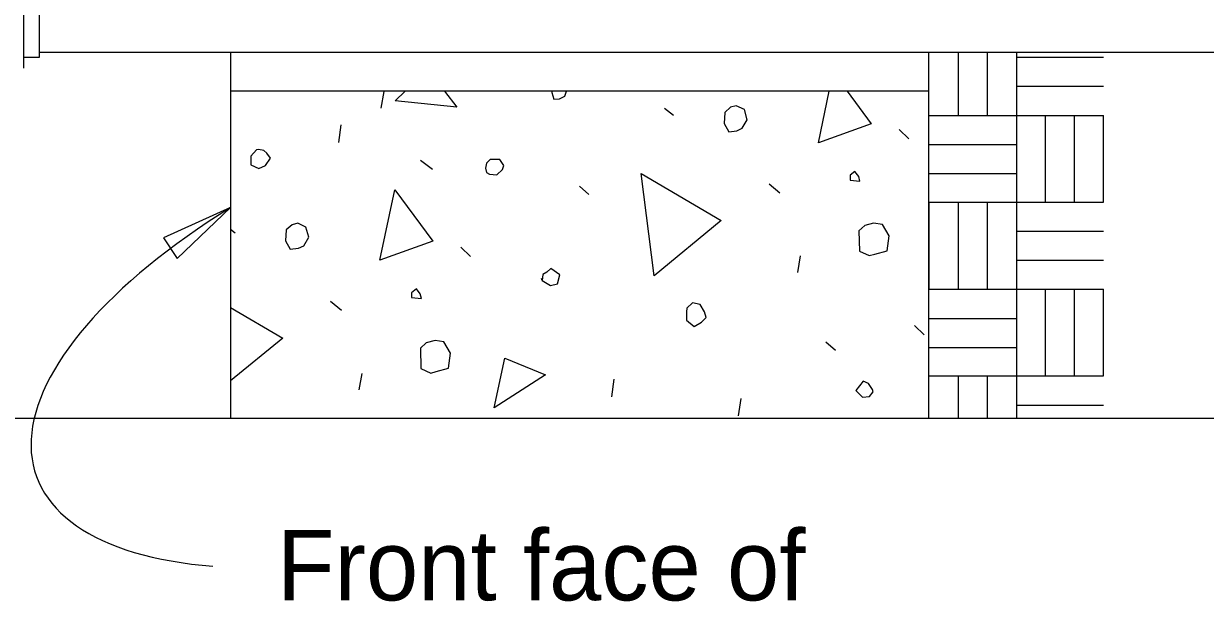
# Model space of a CAD drawing. Extents: x 112544 to 112597.1, y 111084 to 111107.1.
# Drawn here: x 112569.508 to 112572.046, y 111097.897 to 111099.138 of the extents above; entities that cross this region are included whole.
import ezdxf

# ---------------------------------------------------------------- set-up
doc = ezdxf.new("R2010")
doc.units = 0
for name, color, linetype in [('Dimension', 7, 'Continuous'), ('Lighting', 7, 'Continuous'), ('Miscellaneous', 7, 'Continuous'), ('SupstrConc', 7, 'Continuous')]:
    doc.layers.add(name, color=color, linetype=linetype)

msp = doc.modelspace()

# ---------------------------------------------------------------- linework, layer by layer
at = {"layer": 'Dimension'}
msp.add_lwpolyline([(112569.9525, 111098.7429), (112569.8082, 111098.6775), (112569.8378, 111098.6336)], close=True, dxfattribs=at)
msp.add_lwpolyline([(112572.7335, 111098.2898), (112569.4119, 111098.2898), (112569.4119, 111098.3673), (112569.3781, 111098.2898), (112569.3444, 111098.2123), (112569.3444, 111098.2898), (112564.9314, 111098.2898)], dxfattribs=at)
msp.add_ellipse((112570.5602, 111098.5306), major_axis=(1.0252, 0.3641), ratio=0.417881, start_param=2.049946, end_param=3.892568, dxfattribs=at)
at = {"layer": 'Lighting'}
for p, q in [((112569.5079, 111099.1926), (112569.5079, 111099.0427)), ((112569.5413, 111099.1697), (112569.5413, 111099.0655)), ((112569.5413, 111099.0655), (112569.5079, 111099.0655)), ((112572.656, 111099.076), (112569.5413, 111099.076))]:
    msp.add_line(p, q, dxfattribs=at)
at = {"layer": 'Miscellaneous'}
for p, q in [((112571.515, 111099.076), (112571.515, 111098.9411)), ((112571.5775, 111099.076), (112571.5775, 111098.9411)), ((112571.6413, 111098.9411), (112571.6413, 111099.076)), ((112571.6413, 111099.066), (112571.8275, 111099.066)), ((112571.4525, 111098.9927), (112569.9525, 111098.9927)), ((112570.2762, 111098.9566), (112570.2823, 111098.9919)), ((112571.6413, 111099.0035), (112571.8275, 111099.0035)), ((112570.8844, 111098.9566), (112570.9041, 111098.9411)), ((112571.4525, 111098.941), (112571.6413, 111098.941)), ((112571.6413, 111098.5673), (112571.6413, 111098.941)), ((112571.6413, 111098.941), (112571.8275, 111098.941)), ((112571.7025, 111098.7548), (112571.7025, 111098.941)), ((112571.765, 111098.7548), (112571.765, 111098.941)), ((112571.8275, 111098.7548), (112571.8275, 111098.941)), ((112570.1846, 111098.8829), (112570.1901, 111098.9206)), ((112571.3885, 111098.9105), (112571.4095, 111098.8902)), ((112571.4525, 111098.8785), (112571.6413, 111098.8785)), ((112570.3605, 111098.8447), (112570.3863, 111098.8257)), ((112571.4525, 111098.816), (112571.6413, 111098.816)), ((112570.7017, 111098.7886), (112570.722, 111098.7707)), ((112571.1091, 111098.7942), (112571.1325, 111098.7746)), ((112571.4525, 111098.7548), (112571.8275, 111098.7548)), ((112571.4525, 111098.7548), (112571.4525, 111098.5673)), ((112571.515, 111098.7548), (112571.515, 111098.5673)), ((112571.5775, 111098.7548), (112571.5775, 111098.5673)), ((112569.9525, 111098.6965), (112569.9623, 111098.6888)), ((112571.6413, 111098.6923), (112571.8275, 111098.6923)), ((112570.4468, 111098.6581), (112570.4677, 111098.6379)), ((112571.1705, 111098.6036), (112571.1766, 111098.6389)), ((112571.6413, 111098.6298), (112571.8275, 111098.6298)), ((112571.4525, 111098.5673), (112571.6413, 111098.5673)), ((112571.6413, 111098.5673), (112571.8275, 111098.5673)), ((112571.6413, 111098.2898), (112571.6413, 111098.5673)), ((112571.7025, 111098.381), (112571.7025, 111098.5673)), ((112571.765, 111098.381), (112571.765, 111098.5673)), ((112571.8275, 111098.381), (112571.8275, 111098.5673)), ((112570.1673, 111098.5418), (112570.1907, 111098.5222)), ((112571.4525, 111098.5048), (112571.6413, 111098.5048)), ((112571.4211, 111098.4896), (112571.4421, 111098.4693)), ((112571.2313, 111098.4542), (112571.2516, 111098.4364)), ((112571.4525, 111098.4423), (112571.6413, 111098.4423)), ((112570.2288, 111098.3512), (112570.2348, 111098.3865)), ((112570.7712, 111098.3361), (112570.7766, 111098.3738)), ((112571.4525, 111098.381), (112571.8275, 111098.381)), ((112571.515, 111098.3811), (112571.515, 111098.2898)), ((112571.5775, 111098.3811), (112571.5775, 111098.2898)), ((112571.0435, 111098.2952), (112571.049, 111098.3329)), ((112571.6413, 111098.3185), (112571.8275, 111098.3185))]:
    msp.add_line(p, q, dxfattribs=at)
for points in [[(112570.3056, 111098.9723), (112570.3276, 111098.9927)], [(112570.4118, 111098.9927), (112570.4387, 111098.9588), (112570.3056, 111098.9723)], [(112570.6425, 111098.9901), (112570.6464, 111098.9756), (112570.6591, 111098.9764), (112570.6705, 111098.9821), (112570.6741, 111098.9927)], [(112570.6427, 111098.9927), (112570.6425, 111098.9901)], [(112571.215, 111098.8821), (112571.2384, 111098.9927)], [(112571.2768, 111098.9927), (112571.3283, 111098.9228), (112571.215, 111098.8821)], [(112571.0138, 111098.9472), (112571.0123, 111098.9236), (112571.0223, 111098.9055), (112571.0399, 111098.9076), (112571.0513, 111098.9133), (112571.0619, 111098.9317), (112571.0561, 111098.9534), (112571.0384, 111098.9616), (112571.0263, 111098.9584), (112571.0138, 111098.9472)], [(112569.9959, 111098.8531), (112569.9956, 111098.8349), (112570.0134, 111098.8267), (112570.0272, 111098.833), (112570.0385, 111098.849), (112570.0304, 111098.8597), (112570.0236, 111098.8657), (112570.0127, 111098.8679), (112570.0078, 111098.8666), (112569.9959, 111098.8531)], [(112570.5023, 111098.8179), (112570.5084, 111098.8144), (112570.5242, 111098.8135), (112570.5367, 111098.8246), (112570.5396, 111098.8331), (112570.5309, 111098.8463), (112570.5103, 111098.846), (112570.5019, 111098.8386), (112570.4997, 111098.8276), (112570.5023, 111098.8179)], [(112570.862, 111098.596), (112570.834, 111098.8162), (112571.0061, 111098.7148), (112570.862, 111098.596)], [(112571.283, 111098.802), (112571.3043, 111098.7999), (112571.3017, 111098.8096), (112571.2936, 111098.8203), (112571.2829, 111098.8123), (112571.283, 111098.802)], [(112570.2732, 111098.6297), (112570.3052, 111098.7807), (112570.3865, 111098.6705), (112570.2732, 111098.6297)], [(112570.072, 111098.6949), (112570.0706, 111098.6712), (112570.0806, 111098.6532), (112570.0981, 111098.6553), (112570.1095, 111098.6609), (112570.1202, 111098.6793), (112570.1143, 111098.701), (112570.0966, 111098.7092), (112570.0845, 111098.706), (112570.072, 111098.6949)], [(112571.3018, 111098.6931), (112571.3032, 111098.6495), (112571.324, 111098.6395), (112571.336, 111098.6428), (112571.3626, 111098.6499), (112571.3669, 111098.6821), (112571.3526, 111098.7067), (112571.3337, 111098.7094), (112571.3144, 111098.7043), (112571.3018, 111098.6931)], [(112570.6214, 111098.5859), (112570.6398, 111098.5753), (112570.6543, 111098.5791), (112570.6594, 111098.5986), (112570.6404, 111098.6117), (112570.632, 111098.6042), (112570.623, 111098.5992), (112570.6214, 111098.5859), (112570.6201, 111098.5907)], [(112570.3413, 111098.5496), (112570.3625, 111098.5476), (112570.3599, 111098.5572), (112570.3519, 111098.568), (112570.3411, 111098.5599), (112570.3413, 111098.5496)], [(112569.9525, 111098.5284), (112570.0644, 111098.4625), (112569.9525, 111098.3702)], [(112570.9318, 111098.5189), (112570.9315, 111098.5007), (112570.9481, 111098.4871), (112570.9637, 111098.4964), (112570.9739, 111098.5069), (112570.9706, 111098.519), (112570.9613, 111098.5346), (112570.9448, 111098.5379), (112570.9323, 111098.5268), (112570.9318, 111098.5189)], [(112570.3601, 111098.4408), (112570.3614, 111098.3971), (112570.3822, 111098.3872), (112570.3943, 111098.3904), (112570.4208, 111098.3975), (112570.4251, 111098.4297), (112570.4108, 111098.4544), (112570.3919, 111098.4571), (112570.3726, 111098.4519), (112570.3601, 111098.4408)], [(112570.5187, 111098.3125), (112570.5417, 111098.4196), (112570.6291, 111098.3835), (112570.5187, 111098.3125)], [(112571.2955, 111098.3498), (112571.3097, 111098.3355), (112571.3248, 111098.3369), (112571.3325, 111098.3468), (112571.3312, 111098.3516), (112571.3225, 111098.3648), (112571.3109, 111098.3695), (112571.3032, 111098.3596), (112571.2955, 111098.3498)]]:
    msp.add_lwpolyline(points, dxfattribs=at)
at = {"layer": 'SupstrConc'}
for p, q in [((112569.9525, 111099.076), (112569.9525, 111098.2899)), ((112571.4525, 111098.2899), (112571.4525, 111099.076))]:
    msp.add_line(p, q, dxfattribs=at)

# ---------------------------------------------------------------- texts
at = {"layer": 'Dimension'}
msp.add_text('Front face of', height=0.1512, dxfattribs=at).set_placement((112570.0522, 111097.8988))

doc.saveas('drawing.dxf')
